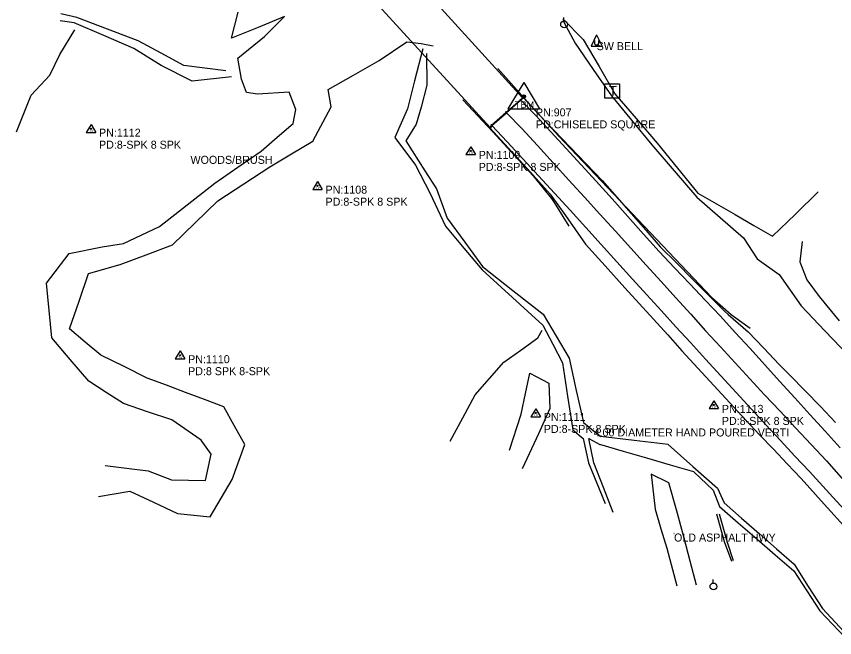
# Model space of a CAD drawing. Extents: x 1193883 to 1197064, y 1474583 to 1477379.
# Drawn here: x 1195296 to 1195807, y 1475658 to 1476046 of the extents above; entities that cross this region are included whole.
import ezdxf

# ---------------------------------------------------------------- set-up
doc = ezdxf.new("R2010")
doc.units = 0
for name, color, linetype in [('S_BRIDGE', 7, 'Continuous'), ('S_DITCHLINE', 7, 'Continuous'), ('S_EDGE_PAVEMENT', 7, 'Continuous'), ('S_GUARDRAIL', 7, 'Continuous'), ('S_LEVEE', 7, 'Continuous'), ('S_MISC_STRUCTURES_ANNOT', 7, 'Continuous'), ('S_MSC_PT_SYM', 7, 'Continuous'), ('S_PAVEMENT_CROWN', 7, 'Continuous'), ('S_PRIMARY_CTL', 7, 'Continuous'), ('S_PRIMARY_CTL_ANNOT', 7, 'Continuous'), ('S_RDW_PT_SYM', 7, 'Continuous'), ('S_SECONDARY_CTL', 7, 'Continuous'), ('S_SECONDARY_CTL_ANNOT', 7, 'Continuous'), ('S_SHOULDER', 7, 'Continuous'), ('S_STR_PT_SYM', 7, 'Continuous'), ('S_STREAM', 7, 'Continuous'), ('S_SURVEY_TEXT_ANNOT', 7, 'Continuous'), ('S_TELEPHONE_UTILITIES', 7, 'Continuous'), ('S_UTILITY_POLE', 7, 'Continuous'), ('S_UTILITY_POLE_ANNOT', 7, 'Continuous')]:
    doc.layers.add(name, color=color, linetype=linetype)

msp = doc.modelspace()

# ---------------------------------------------------------------- linework, layer by layer
at = {"layer": 'S_BRIDGE'}
for p, q in [((1195612.13, 1475995.59), (1195511.19, 1476106.62)), ((1195490.61, 1476087.6), (1195591.91, 1475977.01)), ((1195601.66, 1475986.41), (1195610.85, 1475994.19)), ((1195610.85, 1475994.19), (1195612.13, 1475995.59)), ((1195592.74, 1475978.49), (1195601.66, 1475986.41)), ((1195591.91, 1475977.01), (1195592.74, 1475978.49))]:
    msp.add_line(p, q, dxfattribs=at)
at = {"layer": 'S_DITCHLINE'}
for points in [[(1195426.69, 1476012.38), (1195413.6, 1476014.09), (1195400.5, 1476015.79), (1195386.17, 1476023.45), (1195371.84, 1476031.11), (1195352.65, 1476038.37), (1195333.46, 1476045.64), (1195323.63, 1476048)], [(1195430.31, 1476008.57), (1195405.58, 1476005.92), (1195386.35, 1476015.74), (1195369.12, 1476026.44), (1195350.47, 1476034.39), (1195331.81, 1476042.34), (1195323.12, 1476043.61)], [(1195637.19, 1476044.94), (1195650.03, 1476032.05), (1195659.94, 1476015.07), (1195669.85, 1475998.09), (1195683.07, 1475982.66), (1195696.28, 1475967.24), (1195709.01, 1475951.6), (1195721.74, 1475935.97), (1195733.4, 1475929.24), (1195745.06, 1475922.52), (1195756.72, 1475915.8), (1195768.38, 1475909.08), (1195782.67, 1475922.88), (1195796.95, 1475936.68)], [(1195637.68, 1476043.13), (1195644.89, 1476029.69), (1195656.25, 1476013.24), (1195667.61, 1475996.79), (1195680.24, 1475981.5), (1195692.87, 1475966.2), (1195706.9, 1475949.8), (1195720.94, 1475933.4), (1195735.61, 1475920.76), (1195750.28, 1475908.12), (1195758.73, 1475894.89), (1195772.39, 1475885.06), (1195786.2, 1475865.46), (1195801.09, 1475849.92), (1195815.97, 1475834.37)], [(1195295.75, 1475974.24), (1195305, 1475997.12), (1195316.63, 1476009.73), (1195322.89, 1476022.58), (1195332.2, 1476038.09)], [(1195549.76, 1476026.24), (1195544.49, 1476006.15), (1195540.12, 1475988.71), (1195532.24, 1475970.69), (1195545.13, 1475953.38), (1195554.09, 1475936.07), (1195564.04, 1475915.25), (1195575.45, 1475901.61), (1195586.86, 1475887.97), (1195596.35, 1475879.34), (1195605.84, 1475870.7), (1195615.33, 1475862.06), (1195624.82, 1475853.42), (1195630.96, 1475841.66), (1195637.1, 1475829.9), (1195640.28, 1475808.98), (1195643.47, 1475788.05), (1195649.92, 1475782.51), (1195653.27, 1475767.42), (1195658.51, 1475754.66), (1195663.76, 1475741.89)], [(1195552.09, 1476023.23), (1195552.27, 1476003.4), (1195548.71, 1475989.79), (1195545.61, 1475979.09), (1195539.12, 1475968.67), (1195550.96, 1475949.93), (1195558.34, 1475938.74), (1195565.05, 1475920.4), (1195576.04, 1475905.26), (1195587.02, 1475890.13), (1195606.01, 1475875.2), (1195625, 1475860.27), (1195633.11, 1475846.59), (1195641.22, 1475832.91), (1195645.69, 1475812.71), (1195650.16, 1475792.52), (1195660.83, 1475783.77)], [(1195786.8, 1475905.7), (1195785.34, 1475893.1), (1195789.83, 1475881.86), (1195797.47, 1475871.27), (1195810.02, 1475856.16)], [(1195566.97, 1475781.03), (1195574.75, 1475795.51), (1195582.53, 1475810), (1195591.52, 1475820.17), (1195600.51, 1475830.35), (1195611.11, 1475837.91), (1195621.71, 1475845.47), (1195624.31, 1475850.34)], [(1195668.69, 1475736.46), (1195662.65, 1475751.96), (1195656.6, 1475767.46), (1195653.48, 1475782.51), (1195660.51, 1475778.86)], [(1195703.07, 1475778.82), (1195681.95, 1475781.29), (1195660.83, 1475783.77)], [(1195719.18, 1475761.74), (1195704.51, 1475766.02), (1195689.85, 1475770.3), (1195675.18, 1475774.58), (1195660.51, 1475778.86)], [(1195703.07, 1475778.82), (1195718.53, 1475765.15), (1195734, 1475751.49), (1195738.1, 1475742.5), (1195749.03, 1475732.87), (1195759.96, 1475723.25), (1195770.89, 1475713.62), (1195781.82, 1475703.99), (1195790.71, 1475690.15), (1195799.59, 1475676.3), (1195815.65, 1475659.07)], [(1195719.18, 1475761.74), (1195731.31, 1475750.34), (1195735.28, 1475740.02), (1195746.87, 1475729.98), (1195758.45, 1475719.95), (1195770.04, 1475709.91), (1195781.63, 1475699.87), (1195789.77, 1475687.35), (1195797.91, 1475674.83), (1195813.65, 1475658.16)], [(1195733.34, 1475735.44), (1195738.04, 1475718.24), (1195742.68, 1475706.05)], [(1195734.97, 1475735.63), (1195739.91, 1475717.81), (1195743.72, 1475706.3)]]:
    msp.add_lwpolyline(points, dxfattribs=at)
at = {"layer": 'S_EDGE_PAVEMENT'}
for points in [[(1195592.99, 1475978.21), (1195602.12, 1475986.19), (1195611.03, 1475994.08), (1195620.42, 1475984.4), (1195629.87, 1475974.17), (1195639.32, 1475963.94), (1195648.77, 1475953.71), (1195658.22, 1475943.47), (1195668.06, 1475932.45), (1195677.89, 1475921.43), (1195687.72, 1475910.41), (1195697.55, 1475899.4), (1195707.12, 1475889.31), (1195716.69, 1475879.23), (1195726.26, 1475869.15), (1195735.83, 1475859.07), (1195745.05, 1475848.92), (1195754.27, 1475838.78), (1195763.49, 1475828.64), (1195772.71, 1475818.5), (1195782.2, 1475808.06), (1195791.69, 1475797.62), (1195801.18, 1475787.19), (1195810.67, 1475776.75)], [(1195592.99, 1475978.21), (1195602.39, 1475968.02), (1195612.26, 1475957.35), (1195622.14, 1475946.69), (1195632.02, 1475936.02), (1195641.89, 1475925.35), (1195651.61, 1475914.58), (1195661.33, 1475903.82), (1195671.06, 1475893.05), (1195680.78, 1475882.29), (1195689.83, 1475872.36), (1195698.88, 1475862.43), (1195707.93, 1475852.5), (1195716.98, 1475842.56), (1195726.53, 1475832.17), (1195736.09, 1475821.77), (1195745.64, 1475811.37), (1195755.2, 1475800.98), (1195764.24, 1475791.21), (1195773.29, 1475781.44), (1195782.34, 1475771.67), (1195791.39, 1475761.91), (1195806.07, 1475745.87), (1195820.75, 1475729.84)], [(1195720.78, 1475690.89), (1195716.84, 1475706.03), (1195712.91, 1475721.16), (1195708.27, 1475738.01), (1195703.62, 1475754.86), (1195692.53, 1475760.42), (1195694.95, 1475738.38), (1195698.63, 1475726.25), (1195702.31, 1475714.13), (1195708.52, 1475690.52)]]:
    msp.add_lwpolyline(points, dxfattribs=at)
at = {"layer": 'S_GUARDRAIL'}
for p, q in [((1195596.62, 1476013.87), (1195613.32, 1475995.19)), ((1195574.99, 1475994.13), (1195593.27, 1475974.51)), ((1195613.32, 1475995.19), (1195634.49, 1475971.81)), ((1195593.27, 1475974.51), (1195618.76, 1475946.73)), ((1195634.49, 1475971.81), (1195730.38, 1475870.75)), ((1195618.76, 1475946.73), (1195630.74, 1475931.83)), ((1195630.74, 1475931.83), (1195641.03, 1475915.29)), ((1195730.38, 1475870.75), (1195742.42, 1475860.05)), ((1195742.42, 1475860.05), (1195754.38, 1475851.59))]:
    msp.add_line(p, q, dxfattribs=at)
at = {"layer": 'S_LEVEE'}
msp.add_lwpolyline([(1195604, 1475775.31), (1195611.32, 1475797.88), (1195614.04, 1475810.71), (1195616.76, 1475823.54), (1195628.49, 1475817.13), (1195629.25, 1475801.29), (1195622.14, 1475785.58), (1195611.85, 1475763.65)], dxfattribs=at)
at = {"layer": 'S_MSC_PT_SYM'}
for points in [[(1195404.59, 1475959.27), (1195404.59, 1475959.32), (1195404.59, 1475959.27), (1195404.54, 1475959.27), (1195404.59, 1475959.27), (1195404.59, 1475959.22), (1195404.59, 1475959.27), (1195404.64, 1475959.27)], [(1195656.55, 1475788.89), (1195656.55, 1475788.94), (1195656.55, 1475788.89), (1195656.5, 1475788.89), (1195656.55, 1475788.89), (1195656.55, 1475788.84), (1195656.55, 1475788.89), (1195656.6, 1475788.89)], [(1195706.78, 1475723.22), (1195706.78, 1475723.27), (1195706.78, 1475723.22), (1195706.73, 1475723.22), (1195706.78, 1475723.22), (1195706.78, 1475723.17), (1195706.78, 1475723.22), (1195706.83, 1475723.22)]]:
    msp.add_lwpolyline(points, dxfattribs=at)
at = {"layer": 'S_PAVEMENT_CROWN'}
msp.add_lwpolyline([(1195602.04, 1475986.06), (1195611.68, 1475976.42), (1195621.47, 1475965.67), (1195631.26, 1475954.91), (1195641.05, 1475944.16), (1195650.84, 1475933.41), (1195660.47, 1475922.8), (1195670.1, 1475912.2), (1195679.73, 1475901.6), (1195689.36, 1475891), (1195698.66, 1475880.74), (1195707.96, 1475870.48), (1195717.25, 1475860.22), (1195726.55, 1475849.96), (1195735.77, 1475839.97), (1195744.99, 1475829.97), (1195754.2, 1475819.98), (1195763.42, 1475809.98), (1195773.08, 1475799.63), (1195782.73, 1475789.27), (1195792.39, 1475778.92), (1195802.04, 1475768.56), (1195815.78, 1475753.12)], dxfattribs=at)
at = {"layer": 'S_PRIMARY_CTL'}
for p, q in [((1195612.94, 1476005.15), (1195602.91, 1475988.64)), ((1195612.94, 1476005.15), (1195622.76, 1475988.64)), ((1195602.91, 1475988.64), (1195622.76, 1475988.64))]:
    msp.add_line(p, q, dxfattribs=at)
for radius in [1.04, 0.609, 0.344]:
    msp.add_circle((1195612.94, 1475996.45), radius, dxfattribs=at)
at = {"layer": 'S_RDW_PT_SYM'}
for points in [[(1195596.62, 1476013.87), (1195596.62, 1476013.92), (1195596.62, 1476013.87), (1195596.57, 1476013.87), (1195596.62, 1476013.87), (1195596.62, 1476013.82), (1195596.62, 1476013.87), (1195596.67, 1476013.87)], [(1195574.99, 1475994.13), (1195574.99, 1475994.18), (1195574.99, 1475994.13), (1195574.94, 1475994.13), (1195574.99, 1475994.13), (1195574.99, 1475994.08), (1195574.99, 1475994.13), (1195575.04, 1475994.13)], [(1195613.32, 1475995.19), (1195613.32, 1475995.24), (1195613.32, 1475995.19), (1195613.27, 1475995.19), (1195613.32, 1475995.19), (1195613.32, 1475995.14), (1195613.32, 1475995.19), (1195613.37, 1475995.19)], [(1195593.27, 1475974.51), (1195593.27, 1475974.56), (1195593.27, 1475974.51), (1195593.22, 1475974.51), (1195593.27, 1475974.51), (1195593.27, 1475974.46), (1195593.27, 1475974.51), (1195593.32, 1475974.51)], [(1195634.49, 1475971.81), (1195634.49, 1475971.86), (1195634.49, 1475971.81), (1195634.44, 1475971.81), (1195634.49, 1475971.81), (1195634.49, 1475971.76), (1195634.49, 1475971.81), (1195634.54, 1475971.81)], [(1195618.76, 1475946.73), (1195618.76, 1475946.78), (1195618.76, 1475946.73), (1195618.71, 1475946.73), (1195618.76, 1475946.73), (1195618.76, 1475946.68), (1195618.76, 1475946.73), (1195618.81, 1475946.73)], [(1195630.74, 1475931.83), (1195630.74, 1475931.88), (1195630.74, 1475931.83), (1195630.69, 1475931.83), (1195630.74, 1475931.83), (1195630.74, 1475931.78), (1195630.74, 1475931.83), (1195630.79, 1475931.83)], [(1195641.03, 1475915.29), (1195641.03, 1475915.34), (1195641.03, 1475915.29), (1195640.98, 1475915.29), (1195641.03, 1475915.29), (1195641.03, 1475915.24), (1195641.03, 1475915.29), (1195641.08, 1475915.29)], [(1195730.38, 1475870.75), (1195730.38, 1475870.8), (1195730.38, 1475870.75), (1195730.33, 1475870.75), (1195730.38, 1475870.75), (1195730.38, 1475870.7), (1195730.38, 1475870.75), (1195730.43, 1475870.75)], [(1195742.42, 1475860.05), (1195742.42, 1475860.1), (1195742.42, 1475860.05), (1195742.37, 1475860.05), (1195742.42, 1475860.05), (1195742.42, 1475860), (1195742.42, 1475860.05), (1195742.47, 1475860.05)], [(1195754.38, 1475851.59), (1195754.38, 1475851.64), (1195754.38, 1475851.59), (1195754.33, 1475851.59), (1195754.38, 1475851.59), (1195754.38, 1475851.54), (1195754.38, 1475851.59), (1195754.43, 1475851.59)]]:
    msp.add_lwpolyline(points, dxfattribs=at)
at = {"layer": 'S_SECONDARY_CTL'}
for p, q in [((1195342.4, 1475978.85), (1195339.39, 1475973.89)), ((1195342.4, 1475978.85), (1195345.35, 1475973.89)), ((1195339.39, 1475973.89), (1195345.35, 1475973.89)), ((1195579.71, 1475964.96), (1195576.7, 1475960.01)), ((1195576.7, 1475960.01), (1195582.66, 1475960.01)), ((1195579.71, 1475964.96), (1195582.66, 1475960.01)), ((1195483.97, 1475943.22), (1195480.96, 1475938.27)), ((1195483.97, 1475943.22), (1195486.92, 1475938.27)), ((1195480.96, 1475938.27), (1195486.92, 1475938.27)), ((1195398.07, 1475837.3), (1195395.06, 1475832.35)), ((1195398.07, 1475837.3), (1195401.02, 1475832.35)), ((1195395.06, 1475832.35), (1195401.02, 1475832.35)), ((1195731.68, 1475806.22), (1195728.67, 1475801.26)), ((1195731.68, 1475806.22), (1195734.62, 1475801.26)), ((1195620.39, 1475801.2), (1195617.38, 1475796.25)), ((1195617.38, 1475796.25), (1195623.34, 1475796.25)), ((1195620.39, 1475801.2), (1195623.34, 1475796.25)), ((1195728.67, 1475801.26), (1195734.62, 1475801.26))]:
    msp.add_line(p, q, dxfattribs=at)
for centre, radius in [((1195342.4, 1475976.23), 0.311), ((1195342.4, 1475976.23), 0.183), ((1195342.4, 1475976.23), 0.103), ((1195579.71, 1475962.35), 0.311), ((1195579.71, 1475962.35), 0.183), ((1195579.71, 1475962.35), 0.103), ((1195483.97, 1475940.61), 0.311), ((1195483.97, 1475940.61), 0.183), ((1195483.97, 1475940.61), 0.103), ((1195398.07, 1475834.69), 0.311), ((1195398.07, 1475834.69), 0.183), ((1195398.07, 1475834.69), 0.103), ((1195731.68, 1475803.61), 0.311), ((1195731.68, 1475803.61), 0.183), ((1195731.68, 1475803.61), 0.103), ((1195620.39, 1475798.59), 0.311), ((1195620.39, 1475798.59), 0.183), ((1195620.39, 1475798.59), 0.103)]:
    msp.add_circle(centre, radius, dxfattribs=at)
at = {"layer": 'S_SHOULDER'}
for points in [[(1195611.41, 1475994.76), (1195612.64, 1475995.61), (1195621.85, 1475985.46), (1195631.86, 1475975.06), (1195641.87, 1475964.66), (1195651.87, 1475954.26), (1195661.88, 1475943.86), (1195670.96, 1475933.51), (1195680.04, 1475923.16), (1195689.12, 1475912.82), (1195698.19, 1475902.47), (1195708.23, 1475892.38), (1195718.27, 1475882.29), (1195728.3, 1475872.2), (1195738.34, 1475862.12), (1195740.6, 1475860.07), (1195753.18, 1475849.31), (1195762.84, 1475839.04), (1195772.5, 1475828.76), (1195779.23, 1475822.27), (1195788.74, 1475812.41), (1195798.26, 1475802.54), (1195807.77, 1475792.68)], [(1195592.84, 1475978.01), (1195591.79, 1475976.65), (1195600.75, 1475966.74), (1195615.1, 1475951.05), (1195629.45, 1475935.36), (1195638.85, 1475921.94), (1195651.42, 1475904.11), (1195663.73, 1475890.49), (1195676.03, 1475876.87), (1195684.96, 1475867.02), (1195693.88, 1475857.17), (1195702.81, 1475847.32), (1195711.74, 1475837.47), (1195721.71, 1475826.64), (1195731.69, 1475815.81), (1195741.67, 1475804.97), (1195751.65, 1475794.14), (1195760.3, 1475785), (1195768.94, 1475775.85), (1195777.59, 1475766.71), (1195786.24, 1475757.57), (1195800.63, 1475741.61), (1195815.02, 1475725.65)]]:
    msp.add_lwpolyline(points, dxfattribs=at)
at = {"layer": 'S_STR_PT_SYM'}
for points in [[(1195612.13, 1475995.59), (1195612.13, 1475996.09), (1195612.13, 1475995.59), (1195611.63, 1475995.59), (1195612.13, 1475995.59), (1195612.13, 1475995.09), (1195612.13, 1475995.59), (1195612.63, 1475995.59)], [(1195610.85, 1475994.19), (1195610.85, 1475994.69), (1195610.85, 1475994.19), (1195610.35, 1475994.19), (1195610.85, 1475994.19), (1195610.85, 1475993.69), (1195610.85, 1475994.19), (1195611.35, 1475994.19)], [(1195601.66, 1475986.41), (1195601.66, 1475986.91), (1195601.66, 1475986.41), (1195601.16, 1475986.41), (1195601.66, 1475986.41), (1195601.66, 1475985.91), (1195601.66, 1475986.41), (1195602.16, 1475986.41)], [(1195591.91, 1475977.01), (1195591.91, 1475977.51), (1195591.91, 1475977.01), (1195591.41, 1475977.01), (1195591.91, 1475977.01), (1195591.91, 1475976.51), (1195591.91, 1475977.01), (1195592.41, 1475977.01)], [(1195592.74, 1475978.49), (1195592.74, 1475978.99), (1195592.74, 1475978.49), (1195592.24, 1475978.49), (1195592.74, 1475978.49), (1195592.74, 1475977.99), (1195592.74, 1475978.49), (1195593.24, 1475978.49)]]:
    msp.add_lwpolyline(points, dxfattribs=at)
at = {"layer": 'S_STREAM'}
for points in [[(1195351.25, 1475765.65), (1195364.66, 1475764.01), (1195378.07, 1475762.38), (1195392.78, 1475756.74), (1195413.94, 1475756.32), (1195417.44, 1475772.9), (1195411.17, 1475781.55), (1195392.84, 1475794.22), (1195377.75, 1475799.33), (1195362.65, 1475804.44), (1195351.82, 1475811.42), (1195341, 1475818.39), (1195329.46, 1475831.95), (1195317.93, 1475845.51), (1195316.25, 1475862.65), (1195314.57, 1475879.78), (1195328.82, 1475898.23), (1195349.35, 1475902.4), (1195362.78, 1475904.57), (1195385.27, 1475915.05), (1195402.51, 1475928.64), (1195419.76, 1475942.23), (1195434.23, 1475952.25), (1195448.7, 1475962.27), (1195458.75, 1475970.87), (1195468.81, 1475979.48), (1195470.4, 1475988.25), (1195466.21, 1475999.09), (1195446.47, 1475997.86), (1195439.55, 1475998.81), (1195436.4, 1476007.25), (1195434.26, 1476020.34), (1195450.83, 1476033.75), (1195463.36, 1476046.41), (1195446.83, 1476039.56), (1195430.29, 1476032.71), (1195434.43, 1476049.16)], [(1195347.14, 1475746.42), (1195366.57, 1475749.79), (1195381.47, 1475742.81), (1195396.36, 1475735.84), (1195416.85, 1475733.7), (1195423.73, 1475745.38), (1195430.62, 1475757.05), (1195438.44, 1475778.93), (1195431.91, 1475790.67), (1195425.38, 1475802.41), (1195413.43, 1475806.91), (1195401.47, 1475811.41), (1195389.52, 1475815.91), (1195377.57, 1475820.4), (1195363.04, 1475827.54), (1195348.51, 1475834.68), (1195338.74, 1475842.92), (1195328.97, 1475851.16), (1195334.9, 1475868.44), (1195340.83, 1475885.72), (1195360.54, 1475891.26), (1195376.89, 1475897.48), (1195393.25, 1475903.7), (1195407.51, 1475917.42), (1195421.76, 1475931.14), (1195438, 1475941.79), (1195454.24, 1475952.43), (1195467.67, 1475960.45), (1195481.11, 1475968.46), (1195492.5, 1475989.91), (1195490.56, 1476000.75), (1195506.54, 1476009.77), (1195522.52, 1476018.79), (1195539.8, 1476030.54), (1195548.7, 1476029.47), (1195556.3, 1476028.01)]]:
    msp.add_lwpolyline(points, dxfattribs=at)
at = {"layer": 'S_TELEPHONE_UTILITIES'}
msp.add_lwpolyline([(1195663.6, 1475995.35), (1195663.6, 1476004.35), (1195672.6, 1476004.35), (1195672.6, 1475995.35)], close=True, dxfattribs=at)
at = {"layer": 'S_UTILITY_POLE'}
for p, q in [((1195637.96, 1476043.55), (1195637.96, 1476045.66)), ((1195658.42, 1476034.84), (1195654.9, 1476027.75)), ((1195658.42, 1476034.84), (1195661.91, 1476027.75)), ((1195654.9, 1476027.75), (1195661.91, 1476027.75)), ((1195657.22, 1476028.99), (1195657.22, 1476031.43)), ((1195657.84, 1476028.33), (1195657.22, 1476028.99)), ((1195659.04, 1476028.33), (1195657.84, 1476028.33)), ((1195659.59, 1476028.99), (1195659.04, 1476028.33)), ((1195659.59, 1476031.43), (1195659.59, 1476028.99)), ((1195731.29, 1475692.31), (1195731.29, 1475694.42))]:
    msp.add_line(p, q, dxfattribs=at)
for centre in [(1195638.08, 1476041.41), (1195731.41, 1475690.17)]:
    msp.add_circle(centre, 2.13, dxfattribs=at)

# ---------------------------------------------------------------- texts
at = {"layer": 'S_MISC_STRUCTURES_ANNOT'}
msp.add_text('4.00 DIAMETER HAND POURED VERTI', height=5, dxfattribs=at).set_placement((1195656.55, 1475783.89))
at = {"layer": 'S_PRIMARY_CTL'}
msp.add_text('TBM', height=4.287, rotation=360, dxfattribs=at).set_placement((1195607.29, 1475989.06))
at = {"layer": 'S_PRIMARY_CTL_ANNOT'}
for s, p in [('PN:907', (1195620.44, 1475983.95)), ('PD:CHISELED SQUARE', (1195620.44, 1475976.45))]:
    msp.add_text(s, height=5, dxfattribs=at).set_placement(p)
at = {"layer": 'S_SECONDARY_CTL'}
for p in [(1195341.2, 1475974.22), (1195578.51, 1475960.34), (1195482.76, 1475938.6), (1195396.87, 1475832.68), (1195730.47, 1475801.59), (1195619.19, 1475796.58)]:
    msp.add_text('TV', height=1.5, rotation=360, dxfattribs=at).set_placement(p)
at = {"layer": 'S_SECONDARY_CTL_ANNOT'}
for s, p in [('PN:1112', (1195347.4, 1475971.23)), ('PD:8-SPK 8 SPK', (1195347.4, 1475963.73)), ('PN:1109', (1195584.71, 1475957.35)), ('PD:8-SPK 8 SPK', (1195584.71, 1475949.85)), ('PN:1108', (1195488.97, 1475935.61)), ('PD:8-SPK 8 SPK', (1195488.97, 1475928.11)), ('PN:1110', (1195403.07, 1475829.69)), ('PD:8 SPK 8-SPK', (1195403.07, 1475822.19)), ('PN:1113', (1195736.68, 1475798.61)), ('PN:1111', (1195625.39, 1475793.59)), ('PD:8-SPK 8 SPK', (1195625.39, 1475786.09)), ('PD:8-SPK 8 SPK', (1195736.68, 1475791.11))]:
    msp.add_text(s, height=5, dxfattribs=at).set_placement(p)
at = {"layer": 'S_SURVEY_TEXT_ANNOT'}
for s, p in [('WOODS/BRUSH', (1195404.59, 1475954.27)), ('OLD ASPHALT HWY', (1195706.78, 1475718.22))]:
    msp.add_text(s, height=5, dxfattribs=at).set_placement(p)
at = {"layer": 'S_TELEPHONE_UTILITIES'}
msp.add_text('T', height=6, rotation=360, dxfattribs=at).set_placement((1195666.17, 1475996.85))
at = {"layer": 'S_UTILITY_POLE_ANNOT'}
msp.add_text('SW BELL', height=5, dxfattribs=at).set_placement((1195658.42, 1476025.31))

doc.saveas('drawing.dxf')
